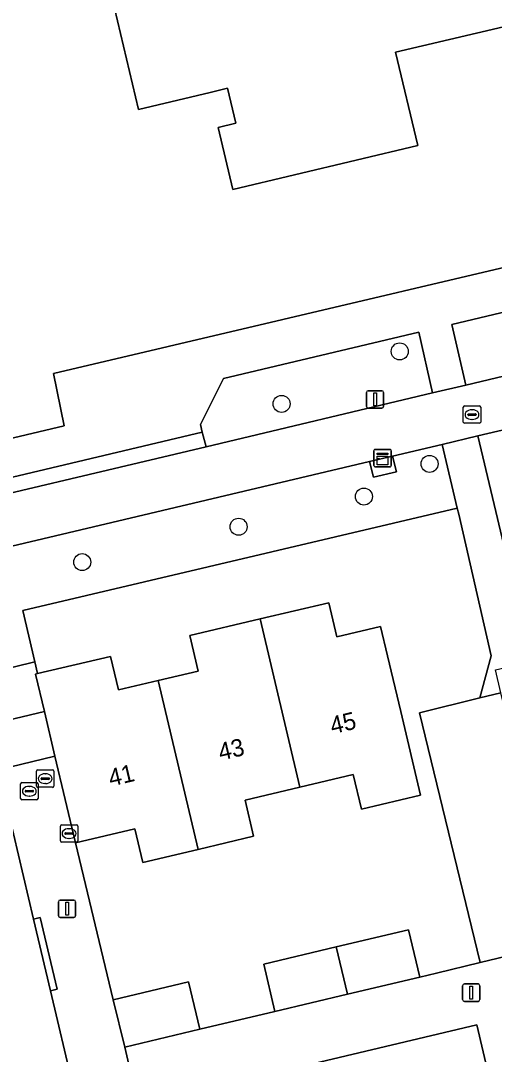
# Model space of a CAD drawing. Extents: x 158031 to 159244, y 380104 to 381214.
# Drawn here: x 158603.7 to 158631, y 380611.4 to 380670.9 of the extents above; entities that cross this region are included whole.
import ezdxf

# ---------------------------------------------------------------- set-up
doc = ezdxf.new("R2010")
doc.units = 0
for name, color, linetype in [('IMGEO_Berm_groen', 7, 'Continuous'), ('IMGEO_Boom', 7, 'Continuous'), ('IMGEO_Brandkraan', 7, 'Continuous'), ('IMGEO_Erf', 7, 'Continuous'), ('IMGEO_Fietspad_open', 7, 'Continuous'), ('IMGEO_Groenvoorziening', 7, 'Continuous'), ('IMGEO_Haag', 7, 'Continuous'), ('IMGEO_Hek', 7, 'Continuous'), ('IMGEO_Kast', 7, 'Continuous'), ('IMGEO_Kolk', 7, 'Continuous'), ('IMGEO_Lichtmast', 7, 'Continuous'), ('IMGEO_Pand', 7, 'Continuous'), ('IMGEO_Pand_nummerreeks', 7, 'Continuous'), ('IMGEO_Parkeervlak_open', 7, 'Continuous'), ('IMGEO_Rioolput', 7, 'Continuous'), ('IMGEO_Terreindeel_open', 7, 'Continuous'), ('IMGEO_Verkeerseiland_open', 7, 'Continuous'), ('IMGEO_Voetpad_open', 7, 'Continuous')]:
    doc.layers.add(name, color=color, linetype=linetype)

msp = doc.modelspace()

# ---------------------------------------------------------------- linework, layer by layer
at = {"layer": 'IMGEO_Berm_groen'}
for points in [[(158643.138, 380653.223), (158642.266, 380653.921), (158639.496, 380656.032), (158628.532, 380653.422), (158629.34, 380649.935)], [(158626.635, 380652.977), (158615.39, 380650.312), (158614.074, 380647.672), (158614.173, 380647.222), (158614.401, 380646.377), (158627.43, 380649.482)], [(158633.446, 380646.922), (158632.592, 380647.598), (158630.034, 380647.004), (158633.114, 380634.023), (158636.393, 380634.638)]]:
    msp.add_lwpolyline(points, close=True, dxfattribs=at)
at = {"layer": 'IMGEO_Boom'}
for centre in [(158625.535, 380651.872), (158618.74, 380648.849), (158627.257, 380645.398), (158623.478, 380643.516), (158616.265, 380641.784), (158607.262, 380639.749)]:
    msp.add_circle(centre, 0.489, dxfattribs=at)
at = {"layer": 'IMGEO_Brandkraan'}
for p, q in [((158603.717, 380626.141), (158603.717, 380626.993)), ((158603.792, 380627.067), (158604.644, 380627.067)), ((158604.718, 380626.993), (158604.718, 380626.141)), ((158603.976, 380626.561), (158603.976, 380626.573)), ((158604.414, 380626.524), (158604.016, 380626.524)), ((158604.019, 380626.61), (158604.417, 380626.61)), ((158604.205, 380626.847), (158604.23, 380626.847)), ((158604.46, 380626.573), (158604.46, 380626.561)), ((158604.644, 380626.067), (158603.792, 380626.067)), ((158604.228, 380626.287), (158604.203, 380626.287))]:
    msp.add_line(p, q, dxfattribs=at)
for points in [[(158603.717, 380626.141), (158603.717, 380626.993)], [(158603.792, 380627.067), (158604.644, 380627.067)], [(158604.718, 380626.993), (158604.718, 380626.141)], [(158604.644, 380626.067), (158603.792, 380626.067)]]:
    msp.add_lwpolyline(points, dxfattribs=at)
for centre, radius, start, end in [((158603.794, 380626.991), 0.0765, 91.55205, 178.44795), ((158603.794, 380626.991), 0.0765, 91.55205, 178.44795), ((158604.642, 380626.991), 0.0765, 1.55205, 88.44795), ((158604.642, 380626.991), 0.0765, 1.55205, 88.44795), ((158604.016, 380626.57), 0.0403, 85.87752, 175.75265), ((158604.013, 380626.56), 0.0366, 178.93798, 274.71019), ((158604.417, 380626.567), 0.043, 264.86636, 352.45326), ((158604.421, 380626.572), 0.0386, 1.73085, 96.63898), ((158603.794, 380626.143), 0.0765, 181.55205, 268.44795), ((158603.794, 380626.143), 0.0765, 181.55205, 268.44795), ((158604.642, 380626.143), 0.0765, 271.55205, 358.44795), ((158604.642, 380626.143), 0.0765, 271.55205, 358.44795)]:
    msp.add_arc(centre, radius, start, end, dxfattribs=at)
for centre, major_axis, ratio, start_param, end_param in [((158604.204, 380626.567), (-0.387, 0.002), 0.722429, 4.712389, 7.853982), ((158604.229, 380626.567), (-0.39, 0.002), 0.717154, 1.570796, 4.712389)]:
    msp.add_ellipse(centre, major_axis=major_axis, ratio=ratio, start_param=start_param, end_param=end_param, dxfattribs=at)
at = {"layer": 'IMGEO_Erf'}
for points in [[(158686.881, 380718.056), (158686.652, 380719.032), (158670.862, 380715.31), (158649.457, 380710.132), (158646.034, 380709.321), (158573.471, 380692.129), (158581.882, 380657.767), (158585.545, 380642.697), (158606.222, 380647.594), (158605.611, 380650.592), (158645.531, 380659.999), (158646.233, 380657.02), (158679.017, 380664.973), (158679.063, 380664.833), (158698.247, 380669.444), (158698.093, 380670.277)], [(158626.679, 380631.073), (158630.155, 380631.932), (158630.8, 380634.354), (158628.933, 380642.507), (158628.853, 380642.842), (158603.837, 380636.964), (158604.535, 380634.009), (158604.696, 380633.332), (158608.891, 380634.325), (158609.348, 380632.396), (158611.625, 380632.936), (158613.936, 380633.483), (158613.454, 380635.518), (158617.496, 380636.476), (158621.451, 380637.413), (158621.918, 380635.444), (158624.434, 380636.04), (158624.833, 380634.358), (158625.593, 380631.147), (158626.73, 380626.349), (158623.334, 380625.544), (158622.863, 380627.533), (158619.789, 380626.804), (158616.645, 380626.059), (158617.114, 380623.976), (158613.928, 380623.216), (158610.759, 380622.461), (158610.298, 380624.408), (158606.883, 380623.594), (158609.046, 380614.568), (158613.379, 380615.592), (158614.031, 380612.869), (158618.353, 380613.893), (158617.707, 380616.618), (158621.877, 380617.606), (158626.047, 380618.594), (158626.693, 380615.87), (158627.647, 380616.095), (158630.162, 380616.722)], [(158618.566, 380598.874), (158617.921, 380601.596), (158623.317, 380602.874), (158622.642, 380605.722), (158628.035, 380607), (158627.714, 380608.355), (158630.92, 380609.117), (158629.973, 380613.126), (158620.191, 380610.816), (158620.842, 380608.092), (158616.603, 380607.079), (158615.952, 380609.802), (158614.725, 380609.51), (158615.373, 380606.786), (158611.144, 380605.772), (158613.13, 380597.614)]]:
    msp.add_lwpolyline(points, close=True, dxfattribs=at)
for points in [[(158660.028, 380673.097), (158661.915, 380665.137), (158655.137, 380663.53), (158640.878, 380660.15), (158638.047, 380672.1), (158625.302, 380669.083), (158626.576, 380663.712), (158615.937, 380661.19), (158615.092, 380664.758), (158616.105, 380664.998), (158615.63, 380667.004), (158614.617, 380666.765), (158610.51, 380665.792), (158608.951, 380672.369)], [(158606.72, 380609.637), (158605.428, 380615.086), (158604.449, 380619.211), (158602.415, 380627.789), (158605.693, 380628.586), (158605.083, 380631.145), (158600.816, 380630.128)]]:
    msp.add_lwpolyline(points, dxfattribs=at)
at = {"layer": 'IMGEO_Fietspad_open'}
msp.add_lwpolyline([(158696.009, 380665.807), (158643.138, 380653.223), (158629.34, 380649.935), (158627.43, 380649.482), (158614.401, 380646.377), (158579.653, 380638.172), (158540.516, 380628.901), (158516.204, 380623.141), (158513.405, 380622.477), (158513.999, 380619.504), (158577.006, 380634.495), (158580.413, 380635.282), (158623.804, 380645.539), (158625.123, 380645.847), (158627.976, 380646.522), (158630.034, 380647.004), (158632.592, 380647.598), (158637.143, 380648.746), (158637.266, 380648.766), (158699.836, 380663.612)], dxfattribs=at)
at = {"layer": 'IMGEO_Groenvoorziening'}
for points in [[(158603.837, 380636.964), (158628.853, 380642.842), (158627.976, 380646.522), (158625.123, 380645.847), (158625.344, 380644.947), (158624.025, 380644.634), (158623.804, 380645.539), (158580.413, 380635.282), (158582.013, 380628.69), (158585.039, 380629.323), (158593.802, 380631.413), (158600.132, 380632.937), (158604.535, 380634.009)], [(158604.449, 380619.211), (158605.428, 380615.086), (158605.817, 380615.178), (158604.838, 380619.303)]]:
    msp.add_lwpolyline(points, close=True, dxfattribs=at)
at = {"layer": 'IMGEO_Haag'}
msp.add_lwpolyline([(158604.449, 380619.211), (158605.428, 380615.086), (158605.817, 380615.178), (158604.838, 380619.303)], close=True, dxfattribs=at)
at = {"layer": 'IMGEO_Hek'}
for points in [[(158698.247, 380669.444), (158679.063, 380664.833), (158679.017, 380664.973), (158646.233, 380657.02), (158645.531, 380659.999), (158605.611, 380650.592), (158606.222, 380647.594), (158585.545, 380642.697), (158581.882, 380657.767)], [(158628.933, 380642.507), (158630.8, 380634.354), (158630.155, 380631.932)], [(158630.155, 380631.932), (158626.679, 380631.073), (158630.162, 380616.722)], [(158609.046, 380614.568), (158606.883, 380623.594)], [(158630.162, 380616.722), (158627.647, 380616.095)], [(158618.353, 380613.893), (158614.031, 380612.869)]]:
    msp.add_lwpolyline(points, dxfattribs=at)
at = {"layer": 'IMGEO_Kast'}
for p, q in [((158624.05, 380645.302), (158624.05, 380646.143)), ((158624.05, 380646.143), (158624.05, 380645.302)), ((158624.125, 380646.227), (158624.966, 380646.227)), ((158624.966, 380646.227), (158624.125, 380646.227)), ((158625.05, 380646.152), (158625.05, 380645.311)), ((158625.05, 380645.311), (158625.05, 380646.152)), ((158624.975, 380645.227), (158624.134, 380645.227)), ((158624.134, 380645.227), (158624.975, 380645.227))]:
    msp.add_line(p, q, dxfattribs=at)
for points in [[(158624.245, 380646.017), (158624.845, 380646.017), (158624.845, 380645.932), (158624.245, 380645.932), (158624.245, 380646.017)], [(158624.245, 380645.842), (158624.845, 380645.842), (158624.845, 380645.353), (158624.245, 380645.353), (158624.245, 380645.842)]]:
    msp.add_lwpolyline(points, dxfattribs=at)
msp.add_circle((158624.329, 380645.691), 0.0377, dxfattribs=at)
for centre, start, end in [((158624.128, 380646.149), 92.4484, 184.28452), ((158624.128, 380646.149), 92.4484, 184.28452), ((158624.972, 380646.149), 2.4484, 94.28452), ((158624.972, 380646.149), 2.4484, 94.28452), ((158624.128, 380645.305), 182.4484, 274.28452), ((158624.128, 380645.305), 182.4484, 274.28452), ((158624.972, 380645.305), 272.4484, 4.28452), ((158624.972, 380645.305), 272.4484, 4.28452)]:
    msp.add_arc(centre, 0.0779, start, end, dxfattribs=at)
at = {"layer": 'IMGEO_Kolk'}
for p, q in [((158606.002, 380623.706), (158606.002, 380624.558)), ((158606.077, 380624.632), (158606.929, 380624.632)), ((158607.003, 380624.558), (158607.003, 380623.706)), ((158606.261, 380624.126), (158606.261, 380624.138)), ((158606.699, 380624.089), (158606.301, 380624.089)), ((158606.304, 380624.175), (158606.702, 380624.175)), ((158606.49, 380624.412), (158606.515, 380624.412)), ((158606.745, 380624.138), (158606.745, 380624.126)), ((158606.929, 380623.632), (158606.077, 380623.632)), ((158606.513, 380623.852), (158606.488, 380623.852))]:
    msp.add_line(p, q, dxfattribs=at)
for points in [[(158606.002, 380623.706), (158606.002, 380624.558)], [(158606.077, 380624.632), (158606.929, 380624.632)], [(158607.003, 380624.558), (158607.003, 380623.706)], [(158606.929, 380623.632), (158606.077, 380623.632)]]:
    msp.add_lwpolyline(points, dxfattribs=at)
for centre, radius, start, end in [((158606.079, 380624.556), 0.0765, 91.55205, 178.44795), ((158606.079, 380624.556), 0.0765, 91.55205, 178.44795), ((158606.927, 380624.556), 0.0765, 1.55205, 88.44795), ((158606.927, 380624.556), 0.0765, 1.55205, 88.44795), ((158606.301, 380624.135), 0.0403, 85.87752, 175.75265), ((158606.298, 380624.125), 0.0366, 178.93798, 274.71019), ((158606.702, 380624.132), 0.043, 264.86636, 352.45326), ((158606.706, 380624.137), 0.0386, 1.73085, 96.63898), ((158606.079, 380623.708), 0.0765, 181.55205, 268.44795), ((158606.079, 380623.708), 0.0765, 181.55205, 268.44795), ((158606.927, 380623.708), 0.0765, 271.55205, 358.44795), ((158606.927, 380623.708), 0.0765, 271.55205, 358.44795)]:
    msp.add_arc(centre, radius, start, end, dxfattribs=at)
for centre, major_axis, ratio, start_param, end_param in [((158606.489, 380624.132), (-0.387, 0.002), 0.722429, 4.712389, 7.853982), ((158606.514, 380624.132), (-0.39, 0.002), 0.717154, 1.570796, 4.712389)]:
    msp.add_ellipse(centre, major_axis=major_axis, ratio=ratio, start_param=start_param, end_param=end_param, dxfattribs=at)
at = {"layer": 'IMGEO_Lichtmast'}
for p, q in [((158623.721, 380649.607), (158624.511, 380649.607)), ((158624.511, 380649.607), (158623.721, 380649.607)), ((158623.621, 380648.707), (158623.621, 380649.507)), ((158623.621, 380649.507), (158623.621, 380648.707)), ((158624.611, 380649.507), (158624.611, 380648.707)), ((158624.611, 380648.707), (158624.611, 380649.507)), ((158624.511, 380648.607), (158623.721, 380648.607)), ((158623.721, 380648.607), (158624.511, 380648.607)), ((158605.892, 380619.406), (158605.892, 380620.206)), ((158605.892, 380620.206), (158605.892, 380619.406)), ((158605.992, 380620.306), (158606.782, 380620.306)), ((158606.782, 380620.306), (158605.992, 380620.306)), ((158606.882, 380620.206), (158606.882, 380619.406)), ((158606.882, 380619.406), (158606.882, 380620.206)), ((158606.782, 380619.306), (158605.992, 380619.306)), ((158605.992, 380619.306), (158606.782, 380619.306)), ((158629.157, 380614.578), (158629.157, 380615.378)), ((158629.157, 380615.378), (158629.157, 380614.578)), ((158629.257, 380615.478), (158630.047, 380615.478)), ((158630.047, 380615.478), (158629.257, 380615.478)), ((158630.147, 380615.378), (158630.147, 380614.578)), ((158630.147, 380614.578), (158630.147, 380615.378)), ((158630.047, 380614.478), (158629.257, 380614.478)), ((158629.257, 380614.478), (158630.047, 380614.478))]:
    msp.add_line(p, q, dxfattribs=at)
for points in [[(158624.041, 380649.482), (158624.191, 380649.482), (158624.191, 380648.732), (158624.041, 380648.732), (158624.041, 380649.482)], [(158606.312, 380620.181), (158606.462, 380620.181), (158606.462, 380619.431), (158606.312, 380619.431), (158606.312, 380620.181)], [(158629.577, 380615.353), (158629.727, 380615.353), (158629.727, 380614.603), (158629.577, 380614.603), (158629.577, 380615.353)]]:
    msp.add_lwpolyline(points, dxfattribs=at)
for centre, start, end in [((158623.721, 380649.507), 90, 180), ((158623.721, 380649.507), 90, 180), ((158624.511, 380649.507), 0, 90), ((158624.511, 380649.507), 360, 90), ((158623.721, 380648.707), 180, 270), ((158623.721, 380648.707), 180, 270), ((158624.511, 380648.707), 270, 0), ((158624.511, 380648.707), 270, 0), ((158605.992, 380620.206), 90, 180), ((158605.992, 380620.206), 90, 180), ((158606.782, 380620.206), 0, 90), ((158606.782, 380620.206), 360, 90), ((158605.992, 380619.406), 180, 270), ((158605.992, 380619.406), 180, 270), ((158606.782, 380619.406), 270, 0), ((158606.782, 380619.406), 270, 0), ((158629.257, 380615.378), 90, 180), ((158629.257, 380615.378), 90, 180), ((158630.047, 380615.378), 0, 90), ((158630.047, 380615.378), 360, 90), ((158629.257, 380614.578), 180, 270), ((158629.257, 380614.578), 180, 270), ((158630.047, 380614.578), 270, 0), ((158630.047, 380614.578), 270, 0)]:
    msp.add_arc(centre, 0.1, start, end, dxfattribs=at)
at = {"layer": 'IMGEO_Pand'}
msp.add_lwpolyline([(158608.951, 380672.369), (158610.51, 380665.792), (158614.617, 380666.765), (158615.63, 380667.004), (158616.105, 380664.998), (158615.092, 380664.758), (158615.937, 380661.19), (158626.576, 380663.712), (158625.302, 380669.083), (158638.047, 380672.1), (158640.878, 380660.15), (158655.137, 380663.53), (158661.915, 380665.137), (158660.028, 380673.097)], dxfattribs=at)
for points in [[(158619.789, 380626.804), (158622.863, 380627.533), (158623.334, 380625.544), (158626.73, 380626.349), (158625.593, 380631.147), (158624.833, 380634.358), (158624.434, 380636.04), (158621.918, 380635.444), (158621.451, 380637.413), (158617.496, 380636.476)], [(158611.625, 380632.936), (158613.928, 380623.216), (158617.114, 380623.976), (158616.645, 380626.059), (158619.789, 380626.804), (158617.496, 380636.476), (158613.454, 380635.518), (158613.936, 380633.483)], [(158605.083, 380631.145), (158605.693, 380628.586), (158606.883, 380623.594), (158610.298, 380624.408), (158610.759, 380622.461), (158613.928, 380623.216), (158611.625, 380632.936), (158609.348, 380632.396), (158608.891, 380634.325), (158604.696, 380633.332), (158604.572, 380633.303)], [(158605.083, 380631.145), (158604.572, 380633.303), (158604.696, 380633.332), (158604.535, 380634.009), (158600.132, 380632.937), (158600.816, 380630.128)], [(158621.877, 380617.606), (158622.523, 380614.882), (158626.693, 380615.87), (158626.047, 380618.594)], [(158621.877, 380617.606), (158617.707, 380616.618), (158618.353, 380613.893), (158622.523, 380614.882)], [(158614.031, 380612.869), (158613.379, 380615.592), (158609.046, 380614.568), (158609.71, 380611.835)]]:
    msp.add_lwpolyline(points, close=True, dxfattribs=at)
at = {"layer": 'IMGEO_Parkeervlak_open'}
msp.add_lwpolyline([(158631.356, 380632.232), (158630.155, 380631.932), (158626.679, 380631.073), (158630.162, 380616.722), (158634.865, 380617.848)], close=True, dxfattribs=at)
at = {"layer": 'IMGEO_Rioolput'}
for p, q in [((158629.198, 380647.807), (158629.198, 380648.659)), ((158629.273, 380648.733), (158630.125, 380648.733)), ((158629.686, 380648.513), (158629.711, 380648.513)), ((158630.199, 380648.659), (158630.199, 380647.807)), ((158629.457, 380648.227), (158629.457, 380648.239)), ((158629.895, 380648.19), (158629.497, 380648.19)), ((158629.5, 380648.276), (158629.898, 380648.276)), ((158629.709, 380647.953), (158629.684, 380647.953)), ((158629.941, 380648.239), (158629.941, 380648.227)), ((158630.125, 380647.733), (158629.273, 380647.733)), ((158604.632, 380626.865), (158604.632, 380627.717)), ((158604.707, 380627.791), (158605.559, 380627.791)), ((158605.12, 380627.571), (158605.145, 380627.571)), ((158605.633, 380627.717), (158605.633, 380626.865)), ((158604.891, 380627.285), (158604.891, 380627.297)), ((158605.329, 380627.248), (158604.931, 380627.248)), ((158604.934, 380627.334), (158605.332, 380627.334)), ((158605.143, 380627.011), (158605.118, 380627.011)), ((158605.375, 380627.297), (158605.375, 380627.285)), ((158605.559, 380626.791), (158604.707, 380626.791))]:
    msp.add_line(p, q, dxfattribs=at)
for points in [[(158629.198, 380647.807), (158629.198, 380648.659)], [(158629.273, 380648.733), (158630.125, 380648.733)], [(158630.199, 380648.659), (158630.199, 380647.807)], [(158630.125, 380647.733), (158629.273, 380647.733)], [(158604.632, 380626.865), (158604.632, 380627.717)], [(158604.707, 380627.791), (158605.559, 380627.791)], [(158605.633, 380627.717), (158605.633, 380626.865)], [(158605.559, 380626.791), (158604.707, 380626.791)]]:
    msp.add_lwpolyline(points, dxfattribs=at)
for centre, radius, start, end in [((158629.275, 380648.657), 0.0765, 91.55205, 178.44795), ((158629.275, 380648.657), 0.0765, 91.55205, 178.44795), ((158630.123, 380648.657), 0.0765, 1.55205, 88.44795), ((158630.123, 380648.657), 0.0765, 1.55205, 88.44795), ((158629.275, 380647.809), 0.0765, 181.55205, 268.44795), ((158629.275, 380647.809), 0.0765, 181.55205, 268.44795), ((158629.497, 380648.236), 0.0403, 85.87752, 175.75265), ((158629.494, 380648.226), 0.0366, 178.93798, 274.71019), ((158629.898, 380648.233), 0.043, 264.86636, 352.45326), ((158629.902, 380648.238), 0.0386, 1.73085, 96.63898), ((158630.123, 380647.809), 0.0765, 271.55205, 358.44795), ((158630.123, 380647.809), 0.0765, 271.55205, 358.44795), ((158604.709, 380627.715), 0.0765, 91.55205, 178.44795), ((158604.709, 380627.715), 0.0765, 91.55205, 178.44795), ((158605.557, 380627.715), 0.0765, 1.55205, 88.44795), ((158605.557, 380627.715), 0.0765, 1.55205, 88.44795), ((158604.931, 380627.294), 0.0403, 85.87752, 175.75265), ((158604.928, 380627.284), 0.0366, 178.93798, 274.71019), ((158605.332, 380627.291), 0.043, 264.86636, 352.45326), ((158605.336, 380627.296), 0.0386, 1.73085, 96.63898), ((158604.709, 380626.867), 0.0765, 181.55205, 268.44795), ((158604.709, 380626.867), 0.0765, 181.55205, 268.44795), ((158605.557, 380626.867), 0.0765, 271.55205, 358.44795), ((158605.557, 380626.867), 0.0765, 271.55205, 358.44795)]:
    msp.add_arc(centre, radius, start, end, dxfattribs=at)
for centre, major_axis, ratio, start_param, end_param in [((158629.685, 380648.233), (-0.387, 0.002), 0.722429, 4.712389, 7.853982), ((158629.71, 380648.233), (-0.39, 0.002), 0.717154, 1.570796, 4.712389), ((158605.119, 380627.291), (-0.387, 0.002), 0.722429, 4.712389, 7.853982), ((158605.144, 380627.291), (-0.39, 0.002), 0.717154, 1.570796, 4.712389)]:
    msp.add_ellipse(centre, major_axis=major_axis, ratio=ratio, start_param=start_param, end_param=end_param, dxfattribs=at)
at = {"layer": 'IMGEO_Terreindeel_open'}
msp.add_lwpolyline([(158625.123, 380645.847), (158623.804, 380645.539), (158624.025, 380644.634), (158625.344, 380644.947)], close=True, dxfattribs=at)
at = {"layer": 'IMGEO_Verkeerseiland_open'}
msp.add_lwpolyline([(158579.653, 380638.172), (158614.401, 380646.377), (158614.173, 380647.222), (158579.452, 380638.994)], close=True, dxfattribs=at)
at = {"layer": 'IMGEO_Voetpad_open'}
for points in [[(158698.247, 380669.444), (158679.063, 380664.833), (158679.017, 380664.973), (158646.233, 380657.02), (158645.531, 380659.999), (158605.611, 380650.592), (158606.222, 380647.594), (158585.545, 380642.697), (158582.005, 380641.477), (158579.059, 380640.785), (158579.128, 380640.493), (158578.836, 380640.425), (158579.03, 380639.698), (158578.235, 380639.51), (158560.791, 380635.377), (158560.659, 380635.948), (158557.728, 380635.248)], [(158540.301, 380629.746), (158540.516, 380628.901), (158579.653, 380638.172), (158579.452, 380638.994), (158614.173, 380647.222), (158614.074, 380647.672), (158615.39, 380650.312), (158626.635, 380652.977), (158627.43, 380649.482), (158629.34, 380649.935), (158628.532, 380653.422), (158639.496, 380656.032), (158642.266, 380653.921), (158695.817, 380666.633), (158696.009, 380665.807)], [(158688.336, 380630.486), (158683.991, 380629.458), (158679.824, 380628.465), (158675.658, 380627.472), (158671.273, 380626.443), (158667.076, 380625.452), (158662.878, 380624.462), (158658.489, 380623.417), (158654.365, 380622.44), (158650.241, 380621.462), (158649.038, 380621.183), (158646.891, 380620.567), (158642.259, 380619.492), (158634.865, 380617.848), (158630.162, 380616.722), (158627.647, 380616.095), (158626.693, 380615.87), (158622.523, 380614.882), (158618.353, 380613.893), (158614.031, 380612.869), (158609.71, 380611.835), (158610.485, 380608.502)], [(158610.485, 380608.502), (158609.71, 380611.835), (158609.046, 380614.568), (158606.883, 380623.594), (158605.693, 380628.586), (158602.415, 380627.789), (158604.449, 380619.211), (158604.838, 380619.303), (158605.817, 380615.178), (158605.428, 380615.086), (158606.72, 380609.637)], [(158620.191, 380610.816), (158629.973, 380613.126), (158630.92, 380609.117)]]:
    msp.add_lwpolyline(points, dxfattribs=at)
msp.add_lwpolyline([(158630.034, 380647.004), (158627.976, 380646.522), (158628.853, 380642.842), (158628.933, 380642.507), (158630.8, 380634.354), (158630.155, 380631.932), (158631.356, 380632.232), (158631.047, 380633.555), (158633.114, 380634.023)], close=True, dxfattribs=at)

# ---------------------------------------------------------------- texts
at = {"layer": 'IMGEO_Pand_nummerreeks'}
for s, p in [('45', (158621.659, 380629.841)), ('43', (158615.225, 380628.321)), ('41', (158608.902, 380626.828))]:
    msp.add_text(s, height=1, rotation=13.28793, dxfattribs=at).set_placement(p)

doc.saveas('drawing.dxf')
